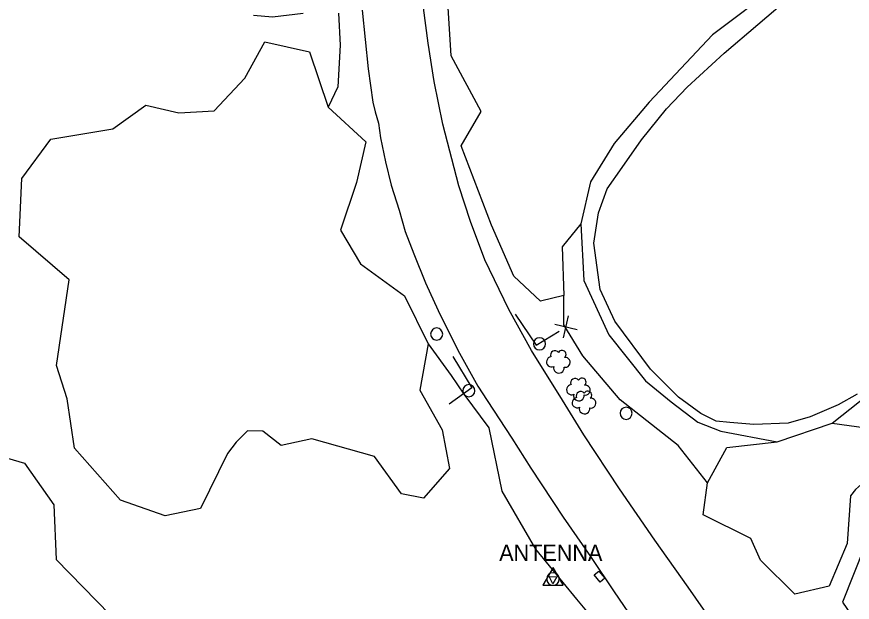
# Model space of a CAD drawing. Extents: x 2160437 to 2172832, y 205694 to 212444.
# Drawn here: x 2171518.5 to 2171725.5, y 206806 to 206951.1 of the extents above; entities that cross this region are included whole.
import ezdxf

# ---------------------------------------------------------------- set-up
doc = ezdxf.new("R2010")
doc.units = 0
for name, color, linetype in [('Default', 7, 'Continuous'), ('RD_EX_Fence_Other', 7, 'Continuous'), ('RD_EX_H2O_Pond', 7, 'Continuous'), ('RD_EX_Misc', 7, 'Continuous'), ('RD_EX_Parking_Paved', 7, 'Continuous'), ('RD_EX_Road', 7, 'Continuous'), ('RD_EX_Road_Post', 7, 'Continuous'), ('RD_EX_UT_Antenna', 7, 'Continuous'), ('RD_EX_VEG', 7, 'Continuous'), ('RD_EX_VEG_ShrubLine', 7, 'Continuous'), ('RD_EX_VEG_TreeLine', 7, 'Continuous')]:
    doc.layers.add(name, color=color, linetype=linetype)

# ---------------------------------------------------------------- blocks, each defined once
blk = doc.blocks.new('ANTENNA')
at = {"layer": 'Default'}
blk.add_lwpolyline([(-0.0417, -0.026), (0.0417, -0.026), (0, 0.0469), (-0.0417, -0.026)], dxfattribs=at)
for start, end in [(90, 270), (270, 90)]:
    blk.add_arc((0, 0), 0.026, start, end, dxfattribs=at)
blk = doc.blocks.new('RD_EX_Fnce_Other')
at = {"layer": 'Default'}
for points in [[(-0.0417, -0.0417), (0.0417, 0.0417)], [(-0.0417, 0.0417), (0.0417, -0.0417)]]:
    blk.add_lwpolyline(points, dxfattribs=at)
blk = doc.blocks.new('POST')
at = {"layer": 'Default'}
for start, end in [(90, 270), (270, 90)]:
    blk.add_arc((0, 0), 0.0417, start, end, dxfattribs=at)

msp = doc.modelspace()

# ---------------------------------------------------------------- linework, layer by layer
at = {"layer": 'RD_EX_Fence_Other'}
for points in [[(2171642, 206877.41), (2171647.26, 206869.69), (2171652.92, 206873.19)], [(2171626.57, 206866.89), (2171631.29, 206859.11), (2171625.66, 206855.13)]]:
    msp.add_lwpolyline(points, dxfattribs=at)
at = {"layer": 'RD_EX_H2O_Pond'}
msp.add_lwpolyline([(2171726.78, 206857.6), (2171722.01, 206854.96), (2171715.08, 206851.95), (2171709.64, 206850.39), (2171701.14, 206850.03), (2171695.18, 206850.54), (2171691.81, 206850.92), (2171688.01, 206852.79), (2171682.46, 206856.87), (2171675.57, 206863.74), (2171666.7, 206875.65), (2171663.12, 206883.49), (2171661.55, 206894.98), (2171662.66, 206902.49), (2171664.78, 206908.42), (2171668.55, 206913.75), (2171673.33, 206920.6), (2171679.52, 206928.28), (2171684.61, 206933.61), (2171693.81, 206942.02), (2171710.44, 206956.31), (2171722.6, 206967.07), (2171736.13, 206978.92)], dxfattribs=at)
at = {"layer": 'RD_EX_Misc'}
for points in [[(2171663.07, 206811.01), (2171661.59, 206812.79), (2171662.76, 206813.76), (2171664.24, 206811.98)], [(2171651.36, 206810.57), (2171650.41, 206812.38), (2171652.38, 206812.34)]]:
    msp.add_lwpolyline(points, close=True, dxfattribs=at)
at = {"layer": 'RD_EX_Parking_Paved'}
msp.add_lwpolyline([(2171731.31, 206826.59), (2171723.15, 206806.04), (2171730.51, 206795.22)], dxfattribs=at)
at = {"layer": 'RD_EX_Road'}
for points in [[(2171604.12, 206952.7), (2171605.64, 206938.11), (2171606.74, 206929.91), (2171607.37, 206927.53), (2171608.17, 206924.73), (2171608.17, 206924.73), (2171608.63, 206921.04), (2171609.89, 206915.13), (2171611.33, 206909.31), (2171613.29, 206903.13), (2171614.77, 206897.85), (2171616.93, 206892.29), (2171619.78, 206885.18), (2171622.92, 206878.26), (2171627.85, 206868.45), (2171632.74, 206859.59), (2171635.13, 206856.01), (2171641.16, 206846.65), (2171645.89, 206839.27), (2171653.95, 206827.11), (2171660.69, 206817.35), (2171666.56, 206808.59), (2171672.42, 206800.07)], [(2171693.05, 206798.09), (2171684.89, 206809.77), (2171676.6, 206821.45), (2171667.85, 206834.11), (2171659.05, 206847.48), (2171653.72, 206856.05), (2171646.06, 206868.36), (2171640.48, 206878.54), (2171634.48, 206890.83), (2171630.94, 206900.35), (2171628.06, 206909.15), (2171624.09, 206924.48), (2171621.92, 206935), (2171620.49, 206944.52), (2171619.3, 206953.25)]]:
    msp.add_lwpolyline(points, dxfattribs=at)
at = {"layer": 'RD_EX_VEG'}
for centre, radius, start, end in [((2171651.88, 206867.27), 1.08, 34.9763, 204.756), ((2171653.65, 206867.42), 0.995, 308.7626, 152.0467), ((2171651.04, 206865.56), 1.26, 96.4518, 294.734), ((2171654.44, 206865.44), 1.22, 256.5667, 98.1046), ((2171652.85, 206864.12), 1.32, 166.8827, 5.7589), ((2171656.84, 206860.39), 1.08, 34.9763, 204.756), ((2171658.61, 206860.54), 0.995, 308.7626, 152.0467), ((2171656, 206858.68), 1.26, 96.4518, 294.734), ((2171659.4, 206858.56), 1.22, 256.5667, 98.1046), ((2171657.81, 206857.24), 1.32, 166.8827, 5.7589), ((2171658.24, 206857.17), 1.08, 34.9763, 204.756), ((2171660.01, 206857.32), 0.995, 308.7626, 152.0467), ((2171657.4, 206855.46), 1.26, 96.4518, 294.734), ((2171660.8, 206855.34), 1.22, 256.5667, 98.1046), ((2171659.21, 206854.02), 1.32, 166.8827, 5.7589)]:
    msp.add_arc(centre, radius, start, end, dxfattribs=at)
at = {"layer": 'RD_EX_VEG_ShrubLine'}
for points in [[(2171577.18, 206951.4), (2171581.93, 206951.03), (2171589.51, 206951.93)], [(2171598.28, 206951.95), (2171598.67, 206943.97), (2171598.1, 206933.65), (2171595.69, 206928.66)], [(2171658.27, 206899.77), (2171659.03, 206885.74), (2171665.25, 206872.29), (2171674.33, 206860.9), (2171680.63, 206855.65), (2171687.26, 206850.67), (2171692.97, 206848.42), (2171706.95, 206845.73)], [(2171689.68, 206835.61), (2171682.38, 206844.85), (2171668.02, 206856.16), (2171658.8, 206867.03), (2171654.12, 206874.75), (2171654.06, 206882.03)], [(2171620.46, 206870.01), (2171626.14, 206862.16), (2171629.29, 206857.61), (2171635.47, 206849.2), (2171638.76, 206833.58), (2171647.1, 206819.16), (2171657.23, 206806.8), (2171663.43, 206799.35)], [(2171720.53, 206850.39), (2171731.72, 206859.25)]]:
    msp.add_lwpolyline(points, dxfattribs=at)
at = {"layer": 'RD_EX_VEG_TreeLine'}
for points in [[(2171707.16, 206958.86), (2171690.91, 206946.55), (2171675.24, 206929.92), (2171666.58, 206919.69), (2171660.71, 206910.2), (2171658.27, 206899.77), (2171653.63, 206894.1), (2171654.06, 206882.03), (2171648.29, 206880.63), (2171641.7, 206886.76), (2171636.2, 206899.45), (2171628.66, 206919.06), (2171633.64, 206927.57), (2171626.19, 206941.37), (2171624.72, 206965.35)], [(2171511.99, 206842.94), (2171520.5, 206840.52), (2171527.7, 206830.15), (2171528.32, 206816.61), (2171541.71, 206802.96), (2171545.38, 206789.09), (2171553.16, 206776.74), (2171556.19, 206769.36), (2171557.13, 206758.87), (2171566.72, 206749.97), (2171572.79, 206739.91), (2171571.12, 206726.99), (2171563.14, 206731.95), (2171552.95, 206740.48), (2171545.28, 206751.71), (2171523.82, 206786.39), (2171501.41, 206818.08)]]:
    msp.add_lwpolyline(points, dxfattribs=at)
for points in [[(2171570.75, 206842.84), (2171564.06, 206829.24), (2171555.34, 206827.48), (2171544.27, 206831.29), (2171532.9, 206844.22), (2171531.02, 206856.42), (2171528.41, 206864.68), (2171531.54, 206885.9), (2171519.12, 206896.54), (2171519.78, 206910.99), (2171527.03, 206920.7), (2171542.33, 206923.28), (2171550.57, 206929.11), (2171558.71, 206927.29), (2171567.47, 206927.75), (2171575.04, 206935.81), (2171580.05, 206944.84), (2171591.08, 206942.33), (2171595.69, 206928.66), (2171605.01, 206920.1), (2171602.73, 206910.03), (2171598.77, 206898.16), (2171603.73, 206889.89), (2171614.59, 206881.9), (2171620.46, 206870.01), (2171618.39, 206858.56), (2171623.93, 206848.74), (2171625.72, 206839.15), (2171619.35, 206831.82), (2171613.84, 206832.86), (2171607.19, 206842.11), (2171591.67, 206846.48), (2171584.07, 206844.84), (2171579.52, 206848.43), (2171575.7, 206848.48), (2171572.92, 206845.7)], [(2171725.07, 206832.37), (2171724.24, 206820.57), (2171719.8, 206809.99), (2171711.3, 206808.02), (2171702.77, 206816.44), (2171700.43, 206821.79), (2171688.59, 206827.67), (2171689.68, 206835.61), (2171694.44, 206844.33), (2171706.95, 206845.73), (2171720.53, 206850.39), (2171729, 206849.27), (2171733.94, 206847.22), (2171732.57, 206839.61), (2171730.09, 206837.23), (2171726.33, 206833.93)]]:
    msp.add_lwpolyline(points, close=True, dxfattribs=at)

# ---------------------------------------------------------------- block references
at = {"layer": 'RD_EX_Fence_Other', "xscale": 47.99999999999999, "yscale": 48, "rotation": 31.748476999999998}
msp.add_blockref('RD_EX_Fnce_Other', (2171654.62, 206874.24), dxfattribs=at)
at = {"layer": 'RD_EX_Road_Post', "xscale": 36, "yscale": 36}
for p in [(2171622.58, 206872.46), (2171648.04, 206870.06), (2171630.55, 206858.43), (2171669.5, 206852.84)]:
    msp.add_blockref('POST', p, dxfattribs=at)
at = {"layer": 'RD_EX_UT_Antenna', "xscale": 60, "yscale": 60}
msp.add_blockref('ANTENNA', (2171651.4, 206811.79), dxfattribs=at)

# ---------------------------------------------------------------- texts
at = {"layer": 'RD_EX_UT_Antenna'}
msp.add_text('ANTENNA', height=4, dxfattribs=at).set_placement((2171638.07, 206816.29))

doc.saveas('drawing.dxf')
